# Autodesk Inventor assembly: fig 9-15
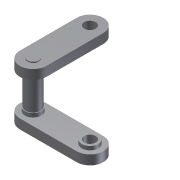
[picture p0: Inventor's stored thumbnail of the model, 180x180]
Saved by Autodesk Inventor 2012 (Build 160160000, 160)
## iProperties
Shininess: 64.0
Length Units: 11269
Angle Units: 11279
Time Units: 11290
Mass Units: 11283
Length Display Precision: 3
Angle Display Precision: 2
Created: 2002-01
Part Number: fig 9-15
Document SubType Name: Assembly
Designer: ***
Density: 0.0
Volumn: 0.0
Area: 0.0
PropertySet Name: Model Information
Control State: 0
Master: False
Checked Out: False
Author: ***
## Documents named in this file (3)
- C:\Users\CadCim\Documents\SAILESH\inventor-2011-fact-prt\c09_inv_2011-prt\c09_inv_2012_prt\fig 9-15.iam
- C:\Users\CadCim\Documents\SAILESH\inventor-2011-fact-prt\c09_inv_2011-prt\c09_inv_2012_prt\Part5.ipt
- C:\Users\CadCim\Documents\SAILESH\inventor-2011-fact-prt\c09_inv_2011-prt\c09_inv_2012_prt\Part6.ipt
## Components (3 placed, 2 different names)
1. Part5:1 — Insert:1, Angle:1
2. Part6:1 — Insert:1, Insert:2
3. Part5:2 — Insert:2, Angle:1
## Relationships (3: Insert 2, Angle 1)
- Insert:1: Part5:1 ↔ Part6:1
- Insert:2: Part6:1 ↔ Part5:2
- Angle:1: Part5:1 ↔ Part5:2
